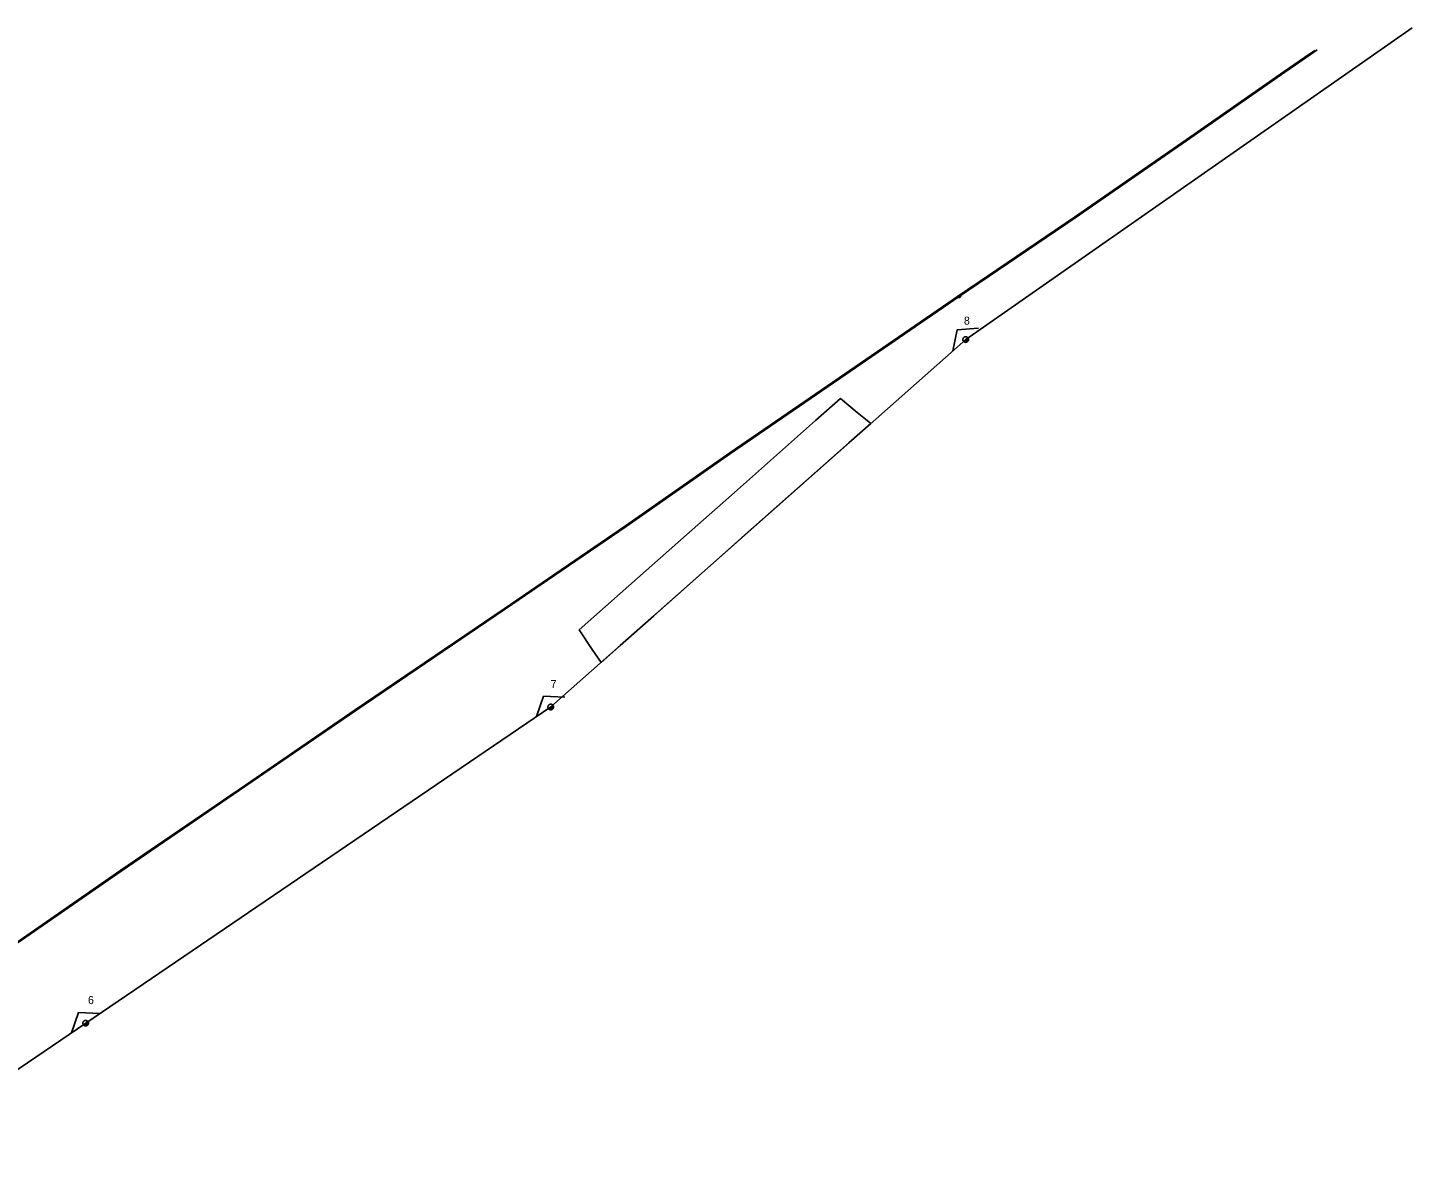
# Model space of a CAD drawing. Extents: x -545588 to -543214, y -1196037 to -1194452.
# Drawn here: x -544817.1 to -544514.3, y -1194697.2 to -1194451.6 of the extents above; entities that cross this region are included whole.
import ezdxf

# ---------------------------------------------------------------- set-up
doc = ezdxf.new("R2010")
doc.units = 0
for name, color, linetype in [('Vrstva 1', 7, 'Continuous'), ('Vrstva 13', 7, 'Continuous'), ('Vrstva 14', 7, 'Continuous'), ('Vrstva 15', 7, 'Continuous'), ('Vrstva 18', 7, 'Continuous'), ('Vrstva 19', 7, 'Continuous'), ('Vrstva 2', 7, 'Continuous'), ('Vrstva 35', 7, 'Continuous'), ('Vrstva 4', 7, 'Continuous'), ('Vrstva 5', 7, 'Continuous')]:
    doc.layers.add(name, color=color, linetype=linetype)

# ---------------------------------------------------------------- blocks, each defined once
blk = doc.blocks.new('VN860')
at = {"layer": 'Vrstva 15'}
for points in [[(-3.74, 0), (0.01, 2.82)], [(0.01, 2.82), (3.76, 0)]]:
    blk.add_lwpolyline(points, dxfattribs=at)
blk = doc.blocks.new('VN440')
at = {"layer": 'Vrstva 2'}
for points in [[(1.22, 0), (1.21, 0.13), (1.19, 0.25), (1.16, 0.38), (1.11, 0.5), (1.05, 0.61), (0.98, 0.72), (0.9, 0.82), (0.81, 0.91), (0.71, 0.99), (0.6, 1.06), (0.49, 1.12), (0.37, 1.16), (0.25, 1.2), (0.12, 1.22), (-0.01, 1.22), (-0.14, 1.22), (-0.26, 1.2), (-0.39, 1.16), (-0.51, 1.12), (-0.62, 1.06), (-0.73, 0.99), (-0.83, 0.91), (-0.92, 0.82), (-1, 0.72), (-1.07, 0.61), (-1.13, 0.5), (-1.18, 0.38), (-1.21, 0.25), (-1.23, 0.13), (-1.24, 0), (-1.23, -0.13), (-1.21, -0.26), (-1.18, -0.38), (-1.13, -0.5), (-1.07, -0.62), (-1, -0.73), (-0.92, -0.83), (-0.83, -0.92), (-0.73, -1), (-0.62, -1.07), (-0.51, -1.13), (-0.39, -1.17), (-0.26, -1.2), (-0.14, -1.23), (-0.01, -1.23), (0.12, -1.23), (0.25, -1.2), (0.37, -1.17), (0.49, -1.13), (0.6, -1.07), (0.71, -1), (0.81, -0.92), (0.9, -0.83), (0.98, -0.73), (1.05, -0.62), (1.11, -0.5), (1.16, -0.38), (1.19, -0.26), (1.21, -0.13), (1.22, 0)], [(-1.24, 0), (1.22, 0)], [(-1.18, -0.34), (1.1, -0.34)], [(-1.01, -0.63), (0.97, -0.63)], [(-0.74, -0.92), (0.68, -0.92)]]:
    blk.add_lwpolyline(points, dxfattribs=at)
blk = doc.blocks.new('VN870')
at = {"layer": 'Vrstva 4'}
for points in [[(0, -0.25), (0.5, 0), (0, 0.25), (-0.5, 0), (0, -0.25)], [(0.37, 0), (0, 0.19), (-0.36, 0), (0, -0.19), (0.37, 0)], [(0.24, 0), (0, 0.12), (-0.25, 0), (0, -0.12), (0.24, 0)], [(0.12, 0), (0, 0.06), (-0.13, 0), (0, -0.06), (0.12, 0)]]:
    blk.add_lwpolyline(points, dxfattribs=at)

msp = doc.modelspace()

# ---------------------------------------------------------------- linework, layer by layer
at = {"layer": 'Vrstva 1'}
msp.add_lwpolyline([(-545096.16, -1194848.04), (-545075.95, -1194854.58), (-545032.81, -1194825.14), (-544993.69, -1194798.32), (-544903.01, -1194736.22), (-544804.37, -1194669.21), (-544702.68, -1194600.1), (-544611.95, -1194519.78), (-544514.29, -1194451.62)], dxfattribs=at)
at = {"layer": 'Vrstva 35'}
msp.add_lwpolyline([(-544673.03, -1194562.5), (-544662.5, -1194553.18), (-544644.79, -1194537.5), (-544639.36, -1194532.69), (-544637.5, -1194534.22), (-544635.7, -1194535.7), (-544633.52, -1194537.5), (-544632.72, -1194538.16), (-544637.5, -1194542.39), (-544660.21, -1194562.5), (-544662.5, -1194564.53), (-544680.17, -1194580.17), (-544687.5, -1194586.66), (-544688.45, -1194587.5), (-544691.68, -1194590.36), (-544693.59, -1194587.5), (-544696.45, -1194583.23), (-544687.5, -1194575.31)], close=True, dxfattribs=at)
at = {"layer": 'Vrstva 5'}
for points in [[(-544879.69, -1194692.19), (-544879.38, -1194692.72), (-544877.42, -1194691.5), (-544872.89, -1194688.33), (-544863.04, -1194681.71), (-544849.25, -1194671.95), (-544823.31, -1194654.21), (-544796.7, -1194635.8), (-544769.45, -1194617.2), (-544745.44, -1194600.7), (-544712.88, -1194578.62), (-544686.33, -1194560.51), (-544663.49, -1194544.51), (-544638.43, -1194527.34), (-544613.5, -1194510.21), (-544588.16, -1194493), (-544563.72, -1194476.13), (-544542.28, -1194461.2), (-544536.69, -1194457.31), (-544535.63, -1194456.59)], [(-544823.19, -1194654.37), (-544796.58, -1194635.96), (-544769.33, -1194617.36), (-544745.32, -1194600.86), (-544712.76, -1194578.78), (-544686.21, -1194560.67), (-544663.37, -1194544.67), (-544638.31, -1194527.5), (-544613.38, -1194510.37), (-544588.04, -1194493.16), (-544563.6, -1194476.29), (-544542.16, -1194461.36), (-544536.57, -1194457.47), (-544535.09, -1194456.46)]]:
    msp.add_lwpolyline(points, dxfattribs=at)

# ---------------------------------------------------------------- block references
at = {"layer": 'Vrstva 13', "xscale": 0.5, "yscale": 0.5}
for p, rotation in [((-544611.95, -1194519.78), 41.517497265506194), ((-544702.68, -1194600.1), 34.17365283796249), ((-544804.37, -1194669.21), 34.21795841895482)]:
    msp.add_blockref('VN440', p, dxfattribs=dict(at, rotation=rotation))
at = {"layer": 'Vrstva 18'}
for p, rotation in [((-544611.95, -1194519.78), 41.51731403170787), ((-544702.68, -1194600.1), 34.17344729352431), ((-544804.37, -1194669.21), 34.217788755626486)]:
    msp.add_blockref('VN860', p, dxfattribs=dict(at, rotation=rotation))
at = {"layer": 'Vrstva 19', "rotation": 34.49339996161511}
msp.add_blockref('VN870', (-544613.38, -1194510.37), dxfattribs=at)

# ---------------------------------------------------------------- texts
at = {"layer": 'Vrstva 14'}
for s, p in [('8', (-544612.34, -1194516.52)), ('7', (-544702.71, -1194595.95)), ('6', (-544803.87, -1194665.04))]:
    msp.add_text(s, height=1.75, dxfattribs=at).set_placement(p)

doc.saveas('drawing.dxf')
